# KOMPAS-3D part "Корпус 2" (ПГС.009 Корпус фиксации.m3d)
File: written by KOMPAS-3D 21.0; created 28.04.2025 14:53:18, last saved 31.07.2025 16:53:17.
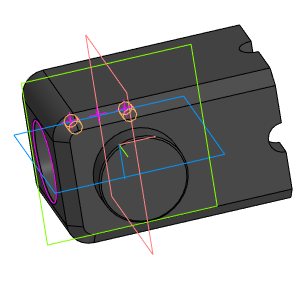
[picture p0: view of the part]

Document properties: Полное имя файла: C:\Users\User\Desktop\ПЕРСПЕКТИВА кд\Модель\ПГС.009 Корпус фиксации.m3d; Автор: User

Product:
- Part/product: Корпус 2
    Масса: 0.699666
    Форматы листов документа: A4@4~2
  - Body: Тело 3
      Масса: 0.703675
  - Body: Тело 1
      Масса: 0.703675

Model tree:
1. Эскиз:1
2. Элемент выдавливания:1
     Расстояние 1 = 43; Расстояние 2 = 22
3. Эскиз:2
4. Элемент вращения:1
     Угол 1 = 360
5. Эскиз:7  (with: Элемент выдавливания:1)
6. Эскиз:8  (with: Элемент выдавливания:1)
7. Элемент выдавливания:8
     Расстояние 2 = 5
8. Эскиз:9  (with: Элемент выдавливания:8)
9. Элемент выдавливания:9
     Расстояние 2 = 10
10. Эскиз:10  (with: Элемент выдавливания:1)
11. Элемент выдавливания:10
     Расстояние 2 = 30
12. Массив по концентрической сетке:2  (with: Элемент выдавливания:10, Эскиз:10, Элемент выдавливания:9)  (4 pattern instances)
     Шаг 2 = 360
13. Эскиз:12
14. Элемент выдавливания:12  (with: Элемент выдавливания:9)
     Расстояние 2 = 50
15. Эскиз:15  (with: Элемент вращения:1)
16. Скругление:1  (with: Элемент выдавливания:1)
     Радиус = 7
17. Фаска:2  (with: Элемент выдавливания:1)
     Угол = 45; Длина 1 = 4; Длина 2 = 4
18. Отверстие:2  (with: Элемент вращения:1)
     Глубина выреза = 3.5; Диаметр отверстия = 10; Угол конуса дна = 118
19. M12  (labels: M12; cil0_24705-2004 coarse)
     Длина резьбы = 7; Шаг резьбы = 1.75; Номинальный диаметр резьбы = 12
20. Отверстие:3  (with: Элемент вращения:1)  (labels: M4)
     Глубина выреза = 9; Диаметр отверстия = 3.24223; Угол конуса дна = 118; Расстояние 2 = 8
21. M4  (with: Элемент вращения:1)  (labels: M4; cil0_24705-2004 coarse)
     Длина резьбы = 6; Шаг резьбы = 0.7; Номинальный диаметр резьбы = 4
22. Отверстие:4  (with: Элемент вращения:1, M4)  (labels: M4; cil0_24705-2004 coarse)
     Глубина выреза = 9; Диаметр отверстия = 3.24223; Угол конуса дна = 118; Расстояние 2 = -8; Длина резьбы = 6; Шаг резьбы = 0.7; Номинальный диаметр резьбы = 4
23. Фаска:3  (with: Элемент выдавливания:9, Элемент выдавливания:12, Элемент вращения:1, Отверстие:2)
     Угол = 45; Длина 1 = 0.5; Длина 2 = 0.5

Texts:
  Точка начала. Х
  Точка начала. Y
  Точка начала. Z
